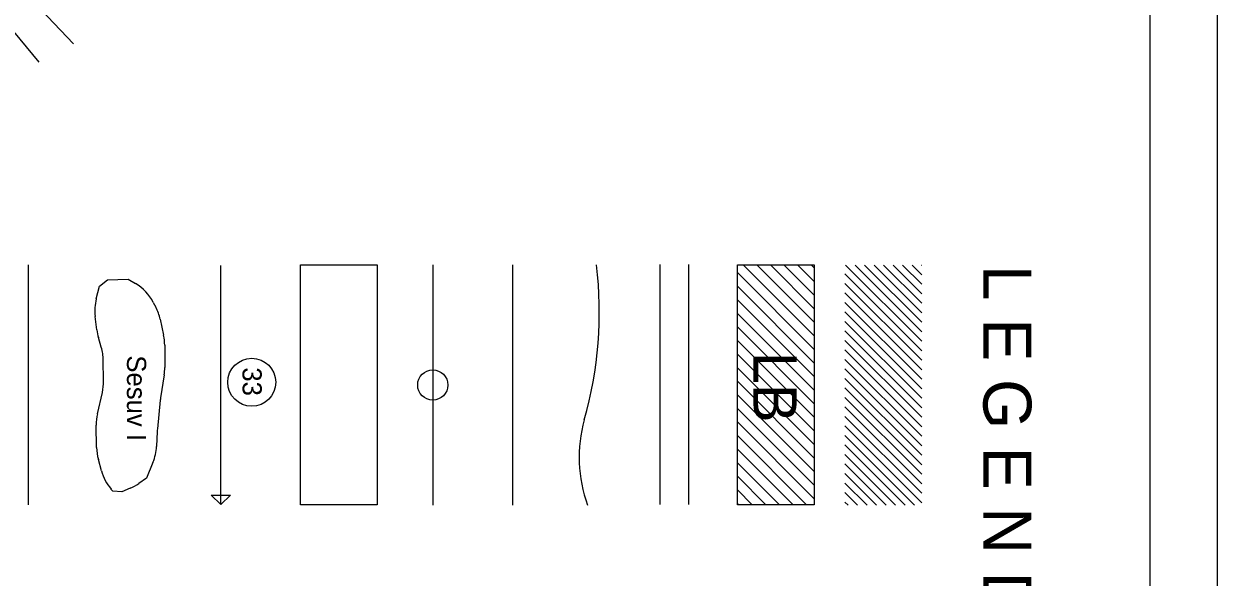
# Model space of a CAD drawing. Extents: x -510989 to -501240, y -1184665 to -1176098.
# Drawn here: x -509263 to -508019, y -1181721 to -1181145 of the extents above; entities that cross this region are included whole.
import ezdxf

# ---------------------------------------------------------------- set-up
doc = ezdxf.new("R2010")
doc.units = 0
for name, color, linetype in [('legenda', 7, 'Continuous'), ('rozpiska', 7, 'Continuous'), ('vrstevnice_01', 7, 'Continuous'), ('vrstevnice_02', 7, 'Continuous')]:
    doc.layers.add(name, color=color, linetype=linetype)

msp = doc.modelspace()

# ---------------------------------------------------------------- linework, layer by layer
at = {"layer": 'legenda'}
for p, q in [((-509258.2, -1181396.08), (-509258.2, -1181646.08)), ((-509057.32, -1181645.91), (-509057.32, -1181396.64)), ((-508836.5, -1181396.19), (-508836.5, -1181646.36)), ((-508753.42, -1181396.19), (-508753.42, -1181646.36)), ((-508599.86, -1181395.77), (-508599.86, -1181645.77)), ((-508569.86, -1181395.77), (-508569.86, -1181645.77)), ((-508512.98, -1181396.19), (-508439.1, -1181470.07)), ((-508498.84, -1181396.19), (-508439.1, -1181455.93)), ((-508484.7, -1181396.19), (-508439.1, -1181441.79)), ((-508470.56, -1181396.19), (-508439.1, -1181427.64)), ((-508456.41, -1181396.19), (-508439.1, -1181413.5)), ((-508442.27, -1181396.19), (-508439.1, -1181399.36)), ((-508406.29, -1181396.36), (-508326.97, -1181475.67)), ((-508396.39, -1181396.36), (-508326.97, -1181465.77)), ((-508386.49, -1181396.36), (-508326.97, -1181455.87)), ((-508376.59, -1181396.36), (-508326.97, -1181445.97)), ((-508366.69, -1181396.36), (-508326.97, -1181436.07)), ((-508356.79, -1181396.36), (-508326.97, -1181426.17)), ((-508346.89, -1181396.36), (-508326.97, -1181416.27)), ((-508336.99, -1181396.36), (-508326.97, -1181406.38)), ((-508327.09, -1181396.36), (-508326.97, -1181396.48)), ((-508519.1, -1181404.21), (-508439.1, -1181484.21)), ((-508406.97, -1181405.57), (-508326.97, -1181485.57)), ((-508519.1, -1181418.35), (-508439.1, -1181498.35)), ((-508406.97, -1181415.47), (-508326.97, -1181495.47)), ((-508406.97, -1181425.37), (-508326.97, -1181505.37)), ((-509127.77, -1181435.17), (-509125.17, -1181440.12)), ((-508519.1, -1181432.5), (-508439.1, -1181512.5)), ((-508406.97, -1181435.27), (-508326.97, -1181515.27)), ((-509186.68, -1181463.73), (-509188.39, -1181449.78)), ((-508519.1, -1181446.64), (-508439.1, -1181526.64)), ((-508406.97, -1181445.17), (-508326.97, -1181525.17)), ((-509120.58, -1181452.79), (-509117, -1181469.37)), ((-508519.1, -1181460.78), (-508439.1, -1181540.78)), ((-508406.97, -1181455.07), (-508326.97, -1181535.07)), ((-509181.99, -1181481.94), (-509184.98, -1181471.91)), ((-508519.1, -1181474.92), (-508439.1, -1181554.92)), ((-508406.97, -1181464.97), (-508326.97, -1181544.97)), ((-508406.97, -1181474.87), (-508326.97, -1181554.87)), ((-509115.88, -1181479.92), (-509115.88, -1181503.1)), ((-508406.97, -1181484.77), (-508326.97, -1181564.77)), ((-509179.57, -1181517.02), (-509179.92, -1181495.39)), ((-508519.1, -1181489.07), (-508439.1, -1181569.07)), ((-508406.97, -1181494.67), (-508326.97, -1181574.67)), ((-509116.46, -1181510.71), (-509120.15, -1181534.7)), ((-508519.1, -1181503.21), (-508439.1, -1181583.21)), ((-508406.97, -1181504.57), (-508326.97, -1181584.57)), ((-508519.1, -1181517.35), (-508439.1, -1181597.35)), ((-508406.97, -1181514.47), (-508326.97, -1181594.47)), ((-508406.97, -1181524.37), (-508326.97, -1181604.37)), ((-509185.93, -1181551.21), (-509180.84, -1181529.02)), ((-509120.47, -1181537.16), (-509123.53, -1181566.78)), ((-508519.1, -1181531.49), (-508439.1, -1181611.49)), ((-508406.97, -1181534.26), (-508326.97, -1181614.26)), ((-508519.1, -1181545.63), (-508439.1, -1181625.63)), ((-508406.97, -1181544.16), (-508326.97, -1181624.16)), ((-508519.1, -1181559.78), (-508439.1, -1181639.78)), ((-508406.97, -1181554.06), (-508326.97, -1181634.06)), ((-509186.83, -1181586.46), (-509187.19, -1181563.18)), ((-509123.75, -1181569.76), (-509124.42, -1181585.22)), ((-508519.1, -1181573.92), (-508446.94, -1181646.08)), ((-508406.97, -1181563.96), (-508326.97, -1181643.96)), ((-508406.97, -1181573.86), (-508334.48, -1181646.36)), ((-508406.97, -1181583.76), (-508344.38, -1181646.36)), ((-509181.82, -1181610.66), (-509185.05, -1181598.92)), ((-508519.1, -1181588.06), (-508461.08, -1181646.08)), ((-508406.97, -1181593.66), (-508354.28, -1181646.36)), ((-508519.1, -1181602.2), (-508475.22, -1181646.08)), ((-508406.97, -1181603.56), (-508364.18, -1181646.36)), ((-508519.1, -1181616.34), (-508489.36, -1181646.08)), ((-508406.97, -1181613.46), (-508374.08, -1181646.36)), ((-508406.97, -1181623.36), (-508383.98, -1181646.36)), ((-508519.1, -1181630.49), (-508503.5, -1181646.08)), ((-508406.97, -1181633.26), (-508393.88, -1181646.36)), ((-508519.1, -1181644.63), (-508517.65, -1181646.08)), ((-508406.97, -1181643.16), (-508403.78, -1181646.36))]:
    msp.add_line(p, q, dxfattribs=at)
for points in [[(-508894.43, -1181396.08), (-508894.43, -1181646.08), (-508974.43, -1181646.08), (-508974.43, -1181396.08)], [(-508439.1, -1181396.08), (-508439.1, -1181646.08), (-508519.1, -1181646.08), (-508519.1, -1181396.08)], [(-509047.31, -1181635.92), (-509057.32, -1181645.91), (-509067.31, -1181635.91)]]:
    msp.add_lwpolyline(points, close=True, dxfattribs=at)
for points in [[(-509187.27, -1181431.56), (-509183.94, -1181418.26), (-509175.57, -1181411.57)], [(-509175.57, -1181411.57), (-509153.81, -1181411.01), (-509146.34, -1181415.49)], [(-509128.1, -1181601.98), (-509134.85, -1181618.46), (-509142.9, -1181623.94)], [(-509151.83, -1181628.78), (-509160.51, -1181632.4), (-509169.99, -1181631.84), (-509171.85, -1181629.64)]]:
    msp.add_lwpolyline(points, dxfattribs=at)
for centre, radius in [((-509025.15, -1181518.42), 25), ((-508836.5, -1181521.27), 15.74)]:
    msp.add_circle(centre, radius, dxfattribs=at)
for centre, radius, start, end in [((-509073.96, -1181445.33), 411, 344.13136, 6.86678), ((-509172.05, -1181458.37), 50, 27.656, 59.047), ((-509138.76, -1181443.7), 50, 165.95802, 186.984), ((-509169.46, -1181463.33), 50, 12.17648, 27.656), ((-509137.05, -1181457.65), 50, 186.984, 196.56373), ((-509165.88, -1181479.92), 50, 0, 12.17648), ((-509229.92, -1181496.2), 50, 0.92444, 16.56373), ((-509165.88, -1181503.1), 50, 351.25017, 0), ((-509229.57, -1181517.83), 50, 347.06868, 0.92444), ((-509070.73, -1181542.3), 50, 171.25017, 174.09136), ((-509137.2, -1181562.39), 50, 167.06868, 180.89555), ((-508541.26, -1181596.76), 142.8, 164.13136, 200.32602), ((-509073.8, -1181571.93), 50, 174.09136, 177.50939), ((-509136.83, -1181585.68), 50, 180.89555, 195.35636), ((-509174.38, -1181583.04), 50, 337.74243, 357.50939), ((-509133.61, -1181597.42), 50, 195.35636, 220.11292), ((-509171.06, -1181582.63), 50, 292.61121, 304.27553)]:
    msp.add_arc(centre, radius, start, end, dxfattribs=at)
at = {"layer": 'rozpiska'}
for points in [[(-508019.09, -1176098), (-508019.09, -1184498), (-510989.09, -1184498), (-510989.09, -1176098)], [(-508089.09, -1176168), (-508089.09, -1184428), (-510919.09, -1184428), (-510919.09, -1176168)]]:
    msp.add_lwpolyline(points, close=True, dxfattribs=at)
at = {"layer": 'vrstevnice_01'}
msp.add_lwpolyline([(-509210.93, -1181165.74), (-509251.41, -1181123), (-509261.19, -1181111), (-509279.5, -1181080), (-509288.41, -1181058), (-509295.09, -1181030), (-509300.81, -1181012), (-509309.31, -1180994), (-509320.69, -1180980)], dxfattribs=at)
at = {"layer": 'vrstevnice_02'}
msp.add_lwpolyline([(-509246.54, -1181184.95), (-509294.91, -1181127), (-509312.31, -1181102), (-509322.19, -1181078), (-509331.91, -1181033), (-509337.69, -1181019), (-509348.31, -1181005), (-509369.41, -1180984), (-509375.31, -1180975)], dxfattribs=at)

# ---------------------------------------------------------------- texts
at = {"layer": 'legenda'}
for s, height, rotation, p in [('L E G E N D A', 50, 269.98112, (-508262.67, -1181396.17)), ('Sesuv I', 20, 270, (-509155.22, -1181490.4)), ('LB', 45, 270.02203, (-508502.35, -1181486.8)), ('33', 20, 270.23741, (-509034.81, -1181502.91))]:
    msp.add_text(s, height=height, rotation=rotation, dxfattribs=at).set_placement(p)

doc.saveas('drawing.dxf')
